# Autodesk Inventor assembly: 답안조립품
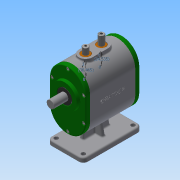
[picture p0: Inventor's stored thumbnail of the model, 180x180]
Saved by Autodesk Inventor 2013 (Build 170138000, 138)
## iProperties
Created: 2018-10
Part Number: 답안조립품
Document SubType Name: Assembly
Designer: Administrator
Author: Administrator
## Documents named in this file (15)
- C:\Users\Administrator\Desktop\381007V1037\답안조립품.iam
- C:\Users\Administrator\Desktop\381007V1037\본체.ipt
- C:\Users\Administrator\Desktop\381007V1037\뒤커버.ipt
- C:\Users\Administrator\Desktop\381007V1037\메인축.ipt
- C:\Users\Administrator\Desktop\381007V1037\베어링 608.ipt
- C:\Users\Administrator\Desktop\381007V1037\베어링 6003.ipt
- C:\Users\Administrator\Desktop\381007V1037\볼트 M4.ipt
- C:\Users\Administrator\Desktop\381007V1037\부시.ipt
- C:\Users\Administrator\Desktop\381007V1037\서브축.ipt
- C:\Users\Administrator\Desktop\381007V1037\슬라이더.ipt
- C:\Users\Administrator\Desktop\381007V1037\앞커버.ipt
- C:\Users\Administrator\Desktop\381007V1037\오일실 8 22 7.ipt
- C:\Users\Administrator\Desktop\381007V1037\오일실 17 32 8.ipt
- C:\Users\Administrator\Desktop\381007V1037\가변스프링1.ipt
- C:\Users\Administrator\Desktop\381007V1037\가변스프링2.ipt
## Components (2 placed, 2 different names)
1. 가변스프링1:1
2. 가변스프링2:1
